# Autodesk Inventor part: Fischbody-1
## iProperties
Shininess: 64.0
Length Units: 11269
Angle Units: 11279
Time Units: 11290
Mass Units: 11283
Length Display Precision: 2
Angle Display Precision: 1
Compacted: True
Part Number: Fischbody-1
Document SubType Name: Modeling
Created: 2004-02
Material: Standard
Designer: Sec
Manufacturer: Standard
Standards Organization: Custom
Density: 0.0
Volumn: 0.0
Area: 0.0
PropertySet Name: Model Information
Control State: 0
Master: False
Checked Out: False
Author: Sec
